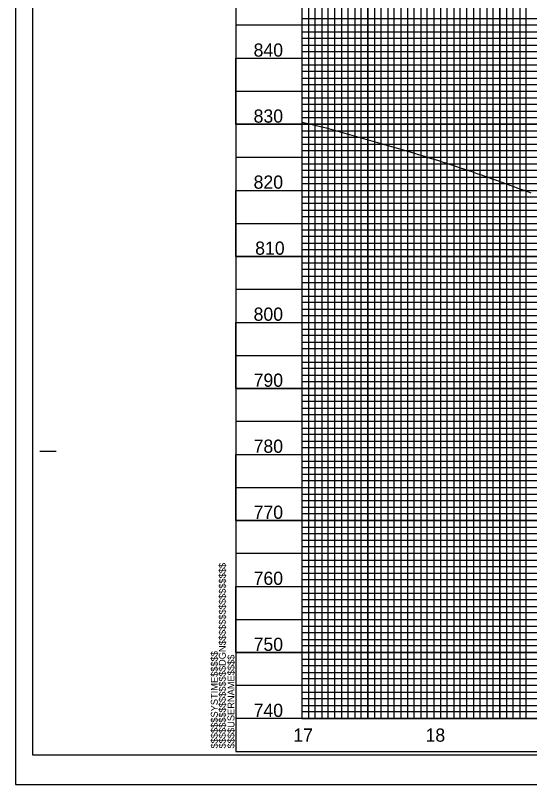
# Model space of a CAD drawing. Extents: x 573566 to 575250, y -53414 to -52314.
# Drawn here: x 573566 to 573956, y -53414 to -52832 of the extents above; entities that cross this region are included whole.
import ezdxf

# ---------------------------------------------------------------- set-up
doc = ezdxf.new("R2010")
doc.units = 0
for name, color, linetype in [('Exist Vertical Profile Ground Line', 7, 'Continuous'), ('Exist Vertical Profile Horizontal Axis Label Major', 7, 'Continuous'), ('Exist Vertical Profile Vertical Axis Label', 7, 'Continuous'), ('Sheet Cutting Line CELL', 7, 'Continuous'), ('Sheet DOT Grid CELL', 7, 'Continuous'), ('Sheet Layout Profile Border', 7, 'Continuous'), ('Sheet Plot Border Inside CELL', 7, 'Continuous'), ('Sheet Plot Border Outside CELL', 7, 'Continuous'), ('Sheet Profile CELL', 7, 'Continuous'), ('Sheet Profile Grid Major CELL', 7, 'Continuous'), ('Sheet Profile Grid Middle CELL', 7, 'Continuous'), ('Sheet Profile Grid Minor CELL', 7, 'Continuous')]:
    doc.layers.add(name, color=color, linetype=linetype)

msp = doc.modelspace()

# ---------------------------------------------------------------- linework, layer by layer
at = {"layer": 'Exist Vertical Profile Ground Line'}
msp.add_lwpolyline([(573783.31, -52912.24), (573783.56, -52912.3), (573801.67, -52916.79), (573817.61, -52921.3), (573817.68, -52921.32), (573833.62, -52925.87), (573833.64, -52925.88), (573847.7, -52929.9), (573847.75, -52929.91), (573859.93, -52933.4), (573861.82, -52933.94), (573862.63, -52934.17), (573865.33, -52934.96), (573866.74, -52935.37), (573868.02, -52935.75), (573870.72, -52936.54), (573871.59, -52936.8), (573871.76, -52936.86), (573873.42, -52937.37), (573876.11, -52938.2), (573878.81, -52939.04), (573881.51, -52939.88), (573884.2, -52940.72), (573886.9, -52941.56), (573889.6, -52942.4), (573890.95, -52942.83), (573891.29, -52942.93), (573892.29, -52943.27), (573894.99, -52944.17), (573897.69, -52945.07), (573900.38, -52945.98), (573903.08, -52946.88), (573905.78, -52947.79), (573908.47, -52948.7), (573911.17, -52949.61), (573913.87, -52950.53), (573916.56, -52951.44), (573919.26, -52952.36), (573920.27, -52952.7), (573920.5, -52952.78), (573920.74, -52952.87), (573921.96, -52953.3), (573924.65, -52954.27), (573927.35, -52955.23), (573928.23, -52955.55), (573930.05, -52956.2), (573932.74, -52957.17), (573935.44, -52958.14), (573938.13, -52959.11), (573940.83, -52960.08), (573943.53, -52961.06), (573943.73, -52961.13), (573946.22, -52962.04), (573948.92, -52963.02), (573949.78, -52963.34), (573949.9, -52963.38), (573951.62, -52964.01), (573954.31, -52965.01), (573956.73, -52965.9)], dxfattribs=at)
at = {"layer": 'Sheet Cutting Line CELL'}
for p, q in [((573566.31, -52314.05), (573566.31, -53414.05)), ((573566.31, -53414.05), (575250.31, -53414.05))]:
    msp.add_line(p, q, dxfattribs=at)
at = {"layer": 'Sheet DOT Grid CELL'}
for p, q in [((573783.31, -52339.05), (573783.31, -53364.05)), ((573833.31, -52339.05), (573833.31, -53364.05)), ((573883.31, -52339.05), (573883.31, -53364.05)), ((573933.31, -52339.05), (573933.31, -53364.05)), ((573733.31, -52864.05), (575233.31, -52864.05)), ((573733.31, -52914.05), (575233.31, -52914.05)), ((573733.31, -52964.05), (575233.31, -52964.05)), ((573733.31, -53014.05), (575233.31, -53014.05)), ((573733.31, -53064.05), (575233.31, -53064.05)), ((573733.31, -53114.05), (575233.31, -53114.05)), ((573733.31, -53164.05), (575233.31, -53164.05)), ((573733.31, -53214.05), (575233.31, -53214.05)), ((573733.31, -53264.05), (575233.31, -53264.05)), ((573733.31, -53314.05), (575233.31, -53314.05))]:
    msp.add_line(p, q, dxfattribs=at)
at = {"layer": 'Sheet Layout Profile Border'}
msp.add_lwpolyline([(573783.31, -52339.05), (573783.31, -53364.05), (575183.31, -53364.05), (575183.31, -52476.6), (575033.26, -52476.6), (575033.26, -52339.05)], close=True, dxfattribs=at)
at = {"layer": 'Sheet Plot Border Inside CELL'}
msp.add_lwpolyline([(575245.81, -52336.5), (573579.31, -52336.5), (573579.31, -53391.6), (575245.81, -53391.6)], close=True, dxfattribs=at)
at = {"layer": 'Sheet Plot Border Outside CELL'}
msp.add_lwpolyline([(575250.31, -52314.05), (573566.31, -52314.05), (573566.31, -53414.05), (575250.31, -53414.05)], close=True, dxfattribs=at)
at = {"layer": 'Sheet Profile CELL'}
for p, q in [((573584.81, -53161.55), (573597.31, -53161.55)), ((575233.31, -53364.05), (573733.31, -53364.05)), ((573733.31, -53389.05), (573733.31, -53389.05)), ((573733.31, -53389.05), (573733.31, -53389.05)), ((573733.31, -53389.05), (573733.31, -53389.05)), ((573733.31, -53389.05), (573733.31, -53389.05)), ((573733.31, -53389.05), (573733.31, -53389.05)), ((573733.31, -53389.05), (573733.31, -53389.05))]:
    msp.add_line(p, q, dxfattribs=at)
msp.add_lwpolyline([(575233.31, -52339.05), (573733.31, -52339.05), (573733.31, -53389.05), (575233.31, -53389.05)], close=True, dxfattribs=at)
msp.add_lwpolyline([(573770.81, -53389.05), (573770.81, -53389.05)], dxfattribs=at)
at = {"layer": 'Sheet Profile Grid Major CELL'}
for points in [[(573783.31, -52339.05), (573783.31, -53364.05), (573833.31, -53364.05), (573833.31, -52339.05)], [(573883.31, -52339.05), (573883.31, -53364.05), (573933.31, -53364.05), (573933.31, -52339.05)], [(575233.31, -52914.05), (573733.31, -52914.05), (573733.31, -52864.05), (575233.31, -52864.05)], [(575233.31, -53014.05), (573733.31, -53014.05), (573733.31, -52964.05), (575233.31, -52964.05)], [(575233.31, -53114.05), (573733.31, -53114.05), (573733.31, -53064.05), (575233.31, -53064.05)], [(575233.31, -53214.05), (573733.31, -53214.05), (573733.31, -53164.05), (575233.31, -53164.05)], [(575233.31, -53314.05), (573733.31, -53314.05), (573733.31, -53264.05), (575233.31, -53264.05)]]:
    msp.add_lwpolyline(points, dxfattribs=at)
at = {"layer": 'Sheet Profile Grid Middle CELL'}
for points in [[(573808.31, -53364.05), (573808.31, -52339.05)], [(573858.31, -52339.05), (573858.31, -53364.05), (573908.31, -53364.05), (573908.31, -52339.05)], [(575233.31, -52839.05), (573733.31, -52839.05), (573733.31, -52889.05), (575233.31, -52889.05)], [(575233.31, -52939.05), (573733.31, -52939.05), (573733.31, -52989.05), (575233.31, -52989.05)], [(575233.31, -53039.05), (573733.31, -53039.05), (573733.31, -53089.05), (575233.31, -53089.05)], [(575233.31, -53139.05), (573733.31, -53139.05), (573733.31, -53189.05), (575233.31, -53189.05)], [(575233.31, -53239.05), (573733.31, -53239.05), (573733.31, -53289.05), (575233.31, -53289.05)], [(575233.31, -53339.05), (573733.31, -53339.05)]]:
    msp.add_lwpolyline(points, dxfattribs=at)
at = {"layer": 'Sheet Profile Grid Minor CELL'}
for points in [[(573788.31, -52339.05), (573788.31, -53364.05), (573793.31, -53364.05), (573793.31, -52339.05)], [(573798.31, -52339.05), (573798.31, -53364.05), (573803.31, -53364.05), (573803.31, -52339.05)], [(573813.31, -52339.05), (573813.31, -53364.05), (573818.31, -53364.05), (573818.31, -52339.05)], [(573823.31, -52339.05), (573823.31, -53364.05), (573828.31, -53364.05), (573828.31, -52339.05)], [(573838.31, -52339.05), (573838.31, -53364.05), (573843.31, -53364.05), (573843.31, -52339.05)], [(573848.31, -52339.05), (573848.31, -53364.05), (573853.31, -53364.05), (573853.31, -52339.05)], [(573863.31, -52339.05), (573863.31, -53364.05), (573868.31, -53364.05), (573868.31, -52339.05)], [(573873.31, -52339.05), (573873.31, -53364.05), (573878.31, -53364.05), (573878.31, -52339.05)], [(573888.31, -52339.05), (573888.31, -53364.05), (573893.31, -53364.05), (573893.31, -52339.05)], [(573898.31, -52339.05), (573898.31, -53364.05), (573903.31, -53364.05), (573903.31, -52339.05)], [(573913.31, -52339.05), (573913.31, -53364.05), (573918.31, -53364.05), (573918.31, -52339.05)], [(573923.31, -52339.05), (573923.31, -53364.05), (573928.31, -53364.05), (573928.31, -52339.05)], [(573938.31, -52339.05), (573938.31, -53364.05), (573943.31, -53364.05), (573943.31, -52339.05)], [(573948.31, -53364.05), (573953.31, -53364.05), (573953.31, -52339.05)], [(573948.31, -52339.05), (573948.31, -53364.05)], [(575183.31, -52834.05), (573783.31, -52834.05), (573783.31, -52844.05), (575183.31, -52844.05)], [(575183.31, -52849.05), (573783.31, -52849.05), (573783.31, -52854.05), (575183.31, -52854.05)], [(575183.31, -52859.05), (573783.31, -52859.05)], [(573783.31, -52869.05), (575183.31, -52869.05)], [(575183.31, -52874.05), (573783.31, -52874.05), (573783.31, -52879.05), (575183.31, -52879.05)], [(575183.31, -52884.05), (573783.31, -52884.05), (573783.31, -52894.05), (575183.31, -52894.05)], [(575183.31, -52899.05), (573783.31, -52899.05), (573783.31, -52904.05), (575183.31, -52904.05)], [(575183.31, -52909.05), (573783.31, -52909.05), (573783.31, -52919.05), (575183.31, -52919.05)], [(575183.31, -52924.05), (573783.31, -52924.05), (573783.31, -52929.05), (575183.31, -52929.05)], [(575183.31, -52934.05), (573783.31, -52934.05), (573783.31, -52944.05), (575183.31, -52944.05)], [(575183.31, -52949.05), (573783.31, -52949.05), (573783.31, -52954.05), (575183.31, -52954.05)], [(575183.31, -52959.05), (573783.31, -52959.05), (573783.31, -52969.05), (575183.31, -52969.05)], [(575183.31, -52974.05), (573783.31, -52974.05), (573783.31, -52979.05), (575183.31, -52979.05)], [(575183.31, -52984.05), (573783.31, -52984.05), (573783.31, -52994.05), (575183.31, -52994.05)], [(575183.31, -52999.05), (573783.31, -52999.05), (573783.31, -53004.05), (575183.31, -53004.05)], [(575183.31, -53009.05), (573783.31, -53009.05), (573783.31, -53019.05), (575183.31, -53019.05)], [(575183.31, -53024.05), (573783.31, -53024.05), (573783.31, -53029.05), (575183.31, -53029.05)], [(575183.31, -53034.05), (573783.31, -53034.05), (573783.31, -53044.05), (575183.31, -53044.05)], [(575183.31, -53049.05), (573783.31, -53049.05), (573783.31, -53054.05), (575183.31, -53054.05)], [(575183.31, -53059.05), (573783.31, -53059.05), (573783.31, -53069.05), (575183.31, -53069.05)], [(575183.31, -53074.05), (573783.31, -53074.05), (573783.31, -53079.05), (575183.31, -53079.05)], [(575183.31, -53084.05), (573783.31, -53084.05), (573783.31, -53094.05), (575183.31, -53094.05)], [(575183.31, -53099.05), (573783.31, -53099.05), (573783.31, -53104.05), (575183.31, -53104.05)], [(575183.31, -53109.05), (573783.31, -53109.05), (573783.31, -53119.05), (575183.31, -53119.05)], [(575183.31, -53124.05), (573783.31, -53124.05), (573783.31, -53129.05), (575183.31, -53129.05)], [(575183.31, -53134.05), (573783.31, -53134.05), (573783.31, -53144.05), (575183.31, -53144.05)], [(575183.31, -53149.05), (573783.31, -53149.05), (573783.31, -53154.05), (575183.31, -53154.05)], [(575183.31, -53159.05), (573783.31, -53159.05)], [(573783.31, -53169.05), (575183.31, -53169.05)], [(575183.31, -53174.05), (573783.31, -53174.05), (573783.31, -53179.05), (575183.31, -53179.05)], [(575183.31, -53184.05), (573783.31, -53184.05)], [(573783.31, -53194.05), (575183.31, -53194.05)], [(575183.31, -53199.05), (573783.31, -53199.05), (573783.31, -53204.05), (575183.31, -53204.05)], [(575183.31, -53209.05), (573783.31, -53209.05), (573783.31, -53219.05), (575183.31, -53219.05)], [(575183.31, -53224.05), (573783.31, -53224.05), (573783.31, -53229.05), (575183.31, -53229.05)], [(575183.31, -53234.05), (573783.31, -53234.05), (573783.31, -53244.05), (575183.31, -53244.05)], [(575183.31, -53249.05), (573783.31, -53249.05), (573783.31, -53254.05), (575183.31, -53254.05)], [(575183.31, -53259.05), (573783.31, -53259.05), (573783.31, -53269.05), (575183.31, -53269.05)], [(575183.31, -53274.05), (573783.31, -53274.05), (573783.31, -53279.05), (575183.31, -53279.05)], [(575183.31, -53284.05), (573783.31, -53284.05), (573783.31, -53294.05), (575183.31, -53294.05)], [(575183.31, -53299.05), (573783.31, -53299.05), (573783.31, -53304.05), (575183.31, -53304.05)], [(575183.31, -53309.05), (573783.31, -53309.05), (573783.31, -53319.05), (575183.31, -53319.05)], [(575183.31, -53324.05), (573783.31, -53324.05), (573783.31, -53329.05), (575183.31, -53329.05)], [(575183.31, -53334.05), (573783.31, -53334.05), (573783.31, -53344.05), (575183.31, -53344.05)], [(575183.31, -53349.05), (573783.31, -53349.05), (573783.31, -53354.05), (575183.31, -53354.05)], [(575183.31, -53359.05), (573783.31, -53359.05)]]:
    msp.add_lwpolyline(points, dxfattribs=at)

# ---------------------------------------------------------------- texts
at = {"layer": 'Exist Vertical Profile Horizontal Axis Label Major'}
for s, p in [('17', (573776.85, -53381.55)), ('18', (573876.97, -53381.55))]:
    msp.add_text(s, height=10, dxfattribs=at).set_placement(p)
at = {"layer": 'Exist Vertical Profile Vertical Axis Label'}
for s, p in [('840', (573746.74, -52862.8)), ('830', (573746.74, -52912.8)), ('820', (573746.74, -52962.8)), ('810', (573747.94, -53012.8)), ('800', (573746.74, -53062.8)), ('790', (573746.74, -53112.8)), ('780', (573746.74, -53162.8)), ('770', (573746.74, -53212.8)), ('760', (573746.74, -53262.8)), ('750', (573746.74, -53312.8)), ('740', (573746.74, -53362.8))]:
    msp.add_text(s, height=10, dxfattribs=at).set_placement(p)
at = {"layer": 'Sheet Profile CELL'}
for s, p in [('$$$$$$$$$$$$$$$$DGN$$$$$$$$$$$$$$$$', (573725.66, -53386.69)), ('$$$$$$SYSTIME$$$$$', (573719.61, -53386.69)), ('$$$$USERNAME$$$$', (573732.23, -53386.67))]:
    msp.add_text(s, height=5.25, rotation=90, dxfattribs=at).set_placement(p)

doc.saveas('drawing.dxf')
